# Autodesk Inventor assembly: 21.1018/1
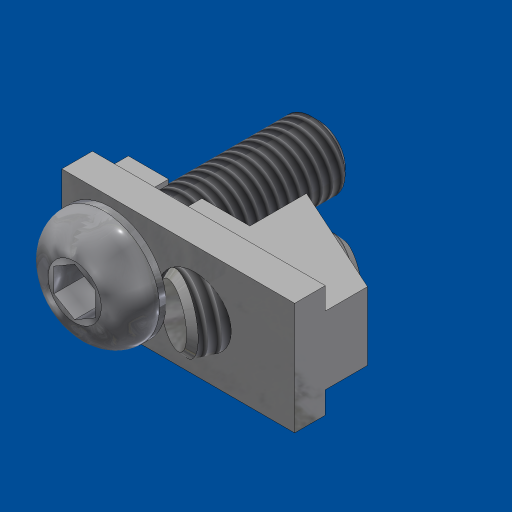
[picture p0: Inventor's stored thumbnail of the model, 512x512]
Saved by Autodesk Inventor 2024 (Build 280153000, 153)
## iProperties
Created: 2006-12
Part Number: 21.1018/1
Document SubType Name: Assembly
Designer: Andy Moles
Mass: 34.3754 g
Surface Area: 35.0271 cm^2
Volume: 4.25438 cm^3
Density: 8.08 g/cm^3
Description: POWER-LOCK SS
Author: Andy Moles
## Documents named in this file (5)
- L:\INVENTOR LIBRARIES\PARTS LIBRARY\FASTENING ELEMENTS\21.1018_1 POWER-LOCK_SS.iam
- 21.1018/1 POWER-LOCK_SS.iam
- L:\INVENTOR LIBRARIES\PARTS LIBRARY\FASTENING ELEMENTS\SUBCOMPONENTS\21.1018_1 POWER-LOCK BODY_SS.ipt
- L:\INVENTOR LIBRARIES\PARTS LIBRARY\FASTENING ELEMENTS\SET SCREWS\21.1301_1 M8X16 SET SCREW FLAT SS.ipt
- L:\INVENTOR LIBRARIES\PARTS LIBRARY\FASTENING ELEMENTS\SCREWS OTHER\21.1189_1 POWER-LOCK SCREW SS.ipt
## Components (3 placed, 3 different names)
1. 21.1018_1 POWER-LOCK BODY_SS:1 — Mate:1, Flush:1, Insert:1
2. 21.1301_1 M8X16 SET SCREW FLAT SS:1 — Mate:1, Flush:1
3. 21.1189_1 POWER-LOCK SCREW SS:1 — Insert:1
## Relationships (3: Mate 1, Flush 1, Insert 1)
- Mate:1: 21.1018_1 POWER-LOCK BODY_SS:1 ↔ 21.1301_1 M8X16 SET SCREW FLAT SS:1
- Flush:1: 21.1018_1 POWER-LOCK BODY_SS:1 ↔ 21.1301_1 M8X16 SET SCREW FLAT SS:1
- Insert:1: 21.1018_1 POWER-LOCK BODY_SS:1 ↔ 21.1189_1 POWER-LOCK SCREW SS:1
